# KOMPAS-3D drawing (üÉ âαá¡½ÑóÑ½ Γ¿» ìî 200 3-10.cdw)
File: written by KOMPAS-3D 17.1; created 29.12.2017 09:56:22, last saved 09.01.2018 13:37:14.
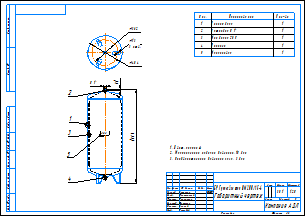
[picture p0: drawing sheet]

Sheet 1: A3, landscape, title-block layout from C:\Лощинин\GRAPHIC.LYT style 1

Title block, sheet 1: name: БР Гранлевел тип НМ 200/1,5-6 / Габаритный чертеж; mass: 38,1; sheets: 1; sheet format: A3; stored path: \\Fsk1\files\АП\20_PKO\02_Насосное направление\Разработка\04_Проекты разные\Баки\КД действующая\Баки Flexcon R\Компас\Чертежи\БР Гранлевел тип НМ 200 1,5-6.cdw; drawn by: Лощинин; checked by: Хантимеров; drawn by, date: 29.12.2017

Views: Проекционный вид 2
Referenced files in \\Fsk1\files\АП\20_PKO\02_Насосное направление\Разработка\04_Проекты разные\Баки\КД действующая\Баки Flexcon R\Компас\: 200 литров.a3d, 16206_Flexcon_200_1-6.m3d
Referenced files in C:\Лощинин\: GRAPHIC.LYT
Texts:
  IvAn
  ADL
  Поз.
  Кол-во
  Корпус бака
  Мембрана SBR
  Патрубок G 1"
  Ниппель
  Маркировка
  АДЛ
  Цвет: красный
  Максимальное рабочее давление: 10 бар
  Предварительное давление газа: 3 бар
  ACAD_ISO03W100_RGB_223_127_255_SC_0.063_THICK_0.05
  ACAD_ISO03W100_RGB_223_127_255_SC_1_THICK_0.05
  Лит-Масса-Масштаб
  Материал-Предприятие
  Масштаб
  Изм.
  Лист
  № докум.
  Подп.
  Дата
  Лит.
  Разраб.
  Пров.
  Т.контр.
  Курлыкина
  Листов
  Нач.отд.
  Щетинин
  Н.контр.
  Долгов
  Утв.
  Рашидов
  Компания АДЛ
  Изменение
  Номер документа
  Подпись
  Обозначение документа
  Наименование изделия
  Масса изделия по ГОСТ 2.109-73
  Порядковый номер листа
  Общее количество листов в документе
  Характер работы, выполненной лицом, подписавшим документ
  Наименование или индекс предприятия, выпускающего документ
  Инв. № подл.
  Подп. и дата
  Взам. инв. №
  Инв. № дубл.
  Инвентарный номер подлинника по ГОСТ 2.501-68
  Подпись принявшего подлинник в отдел технической документации
  Инвентарный номер подлинника, взамен которого выпущен данный подлинник
  Инвентарный номер дубликата по ГОСТ 2.502-68
  Подпись принявшего дубликат в отдел технической документации
  Справ. №
  Перв. примен.
  Обозначение документа, взамен или на основании которого выпущен данный документ
  Обозначение документа, в котором впервые записан данный документ
  Подпись лица, копировавшего чертеж
  Обозначение формата листа
Dimensions and other numbers on the sheet: 1; 3; 2; 4; 5; 1296; 21; 1:20; 38,1; 29.12.2017; 16206_Flexcon_200_1-6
